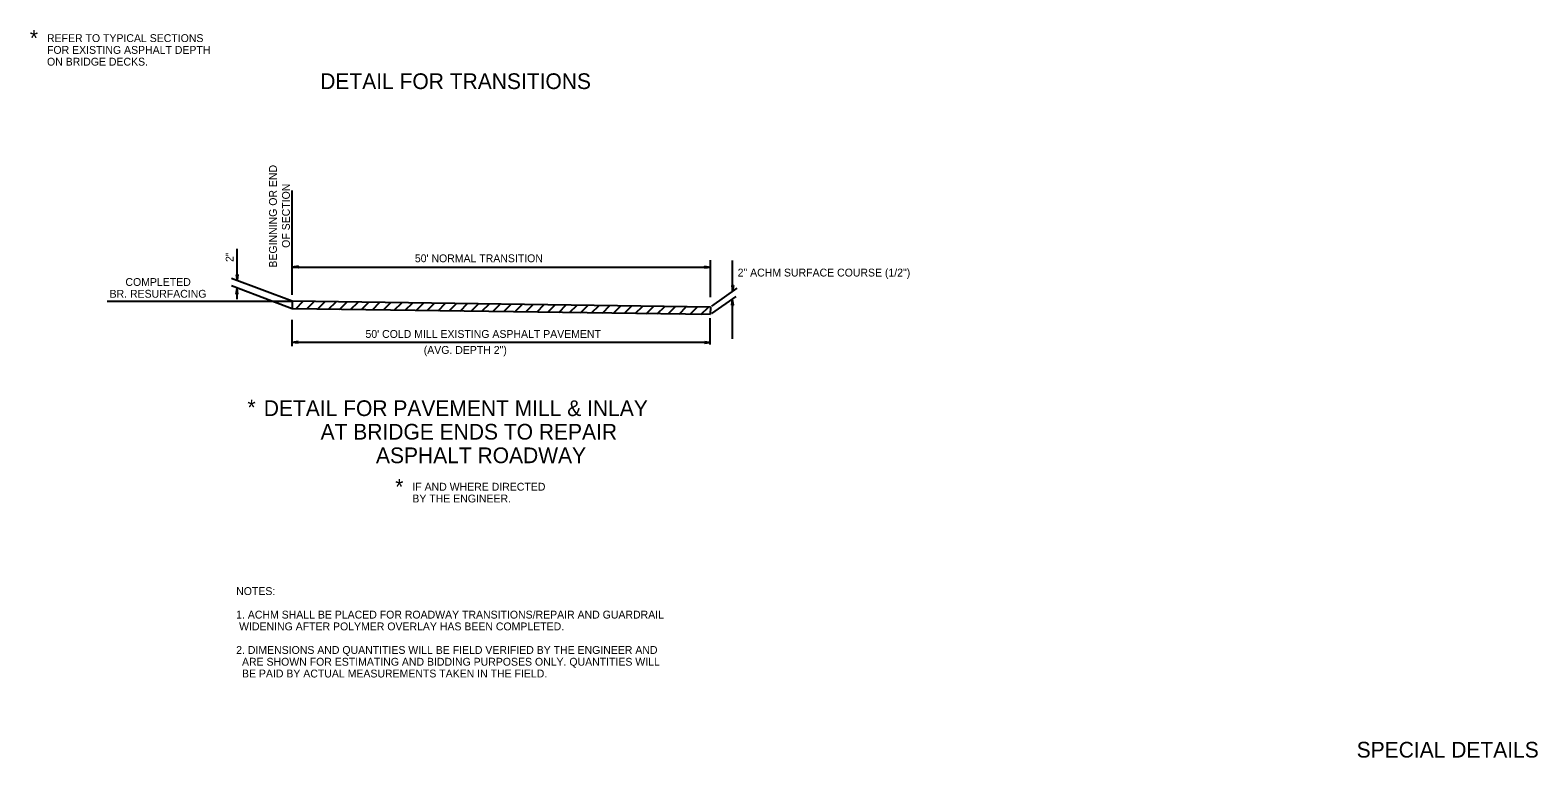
# Model space of a CAD drawing. Extents: x 1931522 to 1935523, y 600380 to 605075.
# Drawn here: x 1933129 to 1934281, y 602208 to 602764 of the extents above; entities that cross this region are included whole.
import ezdxf

# ---------------------------------------------------------------- set-up
doc = ezdxf.new("R2010")
doc.units = 0
doc.layers.add('Default', color=7, linetype='Continuous')
doc.layers.add('R_Border', color=7, linetype='Continuous')

msp = doc.modelspace()

# ---------------------------------------------------------------- linework, layer by layer
at = {"layer": 'Default'}
for p, q in [((1933329.1, 602561.8), (1933329.1, 602641.6)), ((1933286.9, 602573.1), (1933286.9, 602597.1)), ((1933648.6, 602560), (1933648.6, 602588.4)), ((1933665.4, 602564.4), (1933665.4, 602588)), ((1933329.1, 602557.1), (1933282.6, 602574.4)), ((1933286.2, 602577.5), (1933286.9, 602573.1)), ((1933286.2, 602577.5), (1933286.9, 602573.8)), ((1933287.5, 602577.5), (1933286.2, 602577.5)), ((1933286.4, 602577.5), (1933286.9, 602574.7)), ((1933286.4, 602577.5), (1933286.9, 602575.3)), ((1933286.6, 602577.5), (1933286.9, 602576.2)), ((1933286.6, 602577.5), (1933286.9, 602576.9)), ((1933287.5, 602577.5), (1933286.9, 602573.1)), ((1933287.1, 602577.5), (1933286.9, 602576.2)), ((1933287.3, 602577.5), (1933286.9, 602574.7)), ((1933287.3, 602577.5), (1933286.9, 602573.8)), ((1933287.1, 602577.5), (1933286.9, 602575.3)), ((1933286.9, 602577.5), (1933286.9, 602576.9)), ((1933333.7, 602583.8), (1933329.1, 602583.1)), ((1933329.1, 602583.1), (1933648.6, 602583.1)), ((1933333.7, 602582.4), (1933329.1, 602583.1)), ((1933333.7, 602583.5), (1933329.7, 602583.1)), ((1933333.7, 602582.4), (1933329.7, 602583.1)), ((1933333.7, 602583.5), (1933330.6, 602583.1)), ((1933333.7, 602582.6), (1933330.6, 602583.1)), ((1933333.7, 602583.3), (1933331.5, 602583.1)), ((1933333.7, 602582.6), (1933331.5, 602583.1)), ((1933333.7, 602583.3), (1933332.2, 602583.1)), ((1933333.7, 602582.9), (1933332.2, 602583.1)), ((1933333.7, 602583.1), (1933333.1, 602583.1)), ((1933333.7, 602582.9), (1933333.1, 602583.1)), ((1933333.7, 602582.4), (1933333.7, 602583.8)), ((1933643.9, 602583.8), (1933648.6, 602583.1)), ((1933643.9, 602583.8), (1933643.9, 602582.4)), ((1933643.9, 602583.5), (1933647, 602583.1)), ((1933643.9, 602583.5), (1933647.7, 602583.1)), ((1933643.9, 602583.3), (1933645.5, 602583.1)), ((1933643.9, 602583.3), (1933646.1, 602583.1)), ((1933643.9, 602582.4), (1933648.6, 602583.1)), ((1933643.9, 602582.9), (1933645.5, 602583.1)), ((1933643.9, 602582.6), (1933647, 602583.1)), ((1933643.9, 602582.4), (1933647.7, 602583.1)), ((1933643.9, 602582.6), (1933646.1, 602583.1)), ((1933643.9, 602582.9), (1933644.6, 602583.1)), ((1933643.9, 602583.1), (1933644.6, 602583.1)), ((1933313.5, 602557.1), (1933282.6, 602568.7)), ((1933286.2, 602562.4), (1933286.9, 602567.1)), ((1933286.2, 602562.4), (1933286.9, 602566.4)), ((1933286.2, 602562.4), (1933287.5, 602562.4)), ((1933286.4, 602562.4), (1933286.9, 602565.5)), ((1933286.4, 602562.4), (1933286.9, 602564.9)), ((1933286.6, 602562.4), (1933286.9, 602564)), ((1933286.6, 602562.4), (1933286.9, 602563.1)), ((1933287.5, 602562.4), (1933286.9, 602567.1)), ((1933286.9, 602558.7), (1933286.9, 602567.1)), ((1933287.3, 602562.4), (1933286.9, 602566.4)), ((1933287.3, 602562.4), (1933286.9, 602565.5)), ((1933287.1, 602562.4), (1933286.9, 602564.9)), ((1933287.1, 602562.4), (1933286.9, 602564)), ((1933286.9, 602562.4), (1933286.9, 602563.1)), ((1933649.6, 602553.3), (1933669, 602566.9)), ((1933664.8, 602569.1), (1933665.4, 602564.4)), ((1933666.1, 602569.1), (1933664.8, 602569.1)), ((1933665, 602569.1), (1933665.4, 602566)), ((1933665, 602569.1), (1933665.4, 602565.3)), ((1933665.2, 602569.1), (1933665.4, 602567.5)), ((1933665.2, 602569.1), (1933665.4, 602566.9)), ((1933666.1, 602569.1), (1933665.4, 602564.4)), ((1933665.7, 602569.1), (1933665.4, 602567.5)), ((1933665.9, 602569.1), (1933665.4, 602566)), ((1933666.1, 602569.1), (1933665.4, 602565.3)), ((1933665.9, 602569.1), (1933665.4, 602566.9)), ((1933665.4, 602569.1), (1933665.4, 602568.4)), ((1933665.7, 602569.1), (1933665.4, 602568.4)), ((1933187.7, 602557.1), (1933329.1, 602557.1)), ((1933329.1, 602551.3), (1933313.5, 602557.1)), ((1933648.6, 602552.6), (1933329.1, 602557.1)), ((1933648.3, 602546.8), (1933329.1, 602551.3)), ((1933331.7, 602551.3), (1933337.4, 602557)), ((1933340.1, 602551.2), (1933345.8, 602556.9)), ((1933348.5, 602551.1), (1933354.2, 602556.7)), ((1933356.8, 602550.9), (1933362.5, 602556.6)), ((1933365.2, 602550.8), (1933370.9, 602556.5)), ((1933373.6, 602550.7), (1933379.3, 602556.4)), ((1933381.9, 602550.6), (1933387.6, 602556.3)), ((1933390.3, 602550.5), (1933396, 602556.2)), ((1933398.7, 602550.4), (1933404.4, 602556)), ((1933407, 602550.2), (1933412.7, 602555.9)), ((1933415.4, 602550.1), (1933421.1, 602555.8)), ((1933423.8, 602550), (1933429.5, 602555.7)), ((1933432.1, 602549.9), (1933437.8, 602555.6)), ((1933440.5, 602549.8), (1933446.2, 602555.5)), ((1933448.9, 602549.6), (1933454.6, 602555.3)), ((1933457.3, 602549.5), (1933462.9, 602555.2)), ((1933465.6, 602549.4), (1933471.3, 602555.1)), ((1933474, 602549.3), (1933479.7, 602555)), ((1933482.4, 602549.2), (1933488.1, 602554.9)), ((1933490.7, 602549.1), (1933496.4, 602554.8)), ((1933499.1, 602548.9), (1933504.8, 602554.6)), ((1933507.5, 602548.8), (1933513.2, 602554.5)), ((1933515.8, 602548.7), (1933521.5, 602554.4)), ((1933524.2, 602548.6), (1933529.9, 602554.3)), ((1933532.6, 602548.5), (1933538.3, 602554.2)), ((1933540.9, 602548.4), (1933546.6, 602554.1)), ((1933549.3, 602548.2), (1933555, 602553.9)), ((1933557.7, 602548.1), (1933563.4, 602553.8)), ((1933566, 602548), (1933571.7, 602553.7)), ((1933574.4, 602547.9), (1933580.1, 602553.6)), ((1933582.8, 602547.8), (1933588.5, 602553.5)), ((1933591.1, 602547.6), (1933596.8, 602553.3)), ((1933599.5, 602547.5), (1933605.2, 602553.2)), ((1933607.9, 602547.4), (1933613.6, 602553.1)), ((1933616.2, 602547.3), (1933621.9, 602553)), ((1933624.6, 602547.2), (1933630.3, 602552.9)), ((1933633, 602547.1), (1933638.7, 602552.8)), ((1933641.3, 602546.9), (1933647, 602552.6)), ((1933648.6, 602552.7), (1933648.3, 602546.9)), ((1933649.5, 602547.7), (1933668.1, 602560.6)), ((1933664.8, 602554), (1933665.4, 602558.7)), ((1933664.8, 602554), (1933666.1, 602554)), ((1933665, 602554), (1933665.4, 602558)), ((1933665, 602554), (1933665.4, 602557.1)), ((1933665.2, 602554), (1933665.4, 602556.4)), ((1933665.2, 602554), (1933665.4, 602555.5)), ((1933665.4, 602528.4), (1933665.4, 602558.7)), ((1933666.1, 602554), (1933665.4, 602558.7)), ((1933666.1, 602554), (1933665.4, 602558)), ((1933665.9, 602554), (1933665.4, 602557.1)), ((1933665.9, 602554), (1933665.4, 602556.4)), ((1933665.7, 602554), (1933665.4, 602555.5)), ((1933665.7, 602554), (1933665.4, 602554.9)), ((1933665.4, 602554), (1933665.4, 602554.9)), ((1933329.1, 602522.7), (1933329.1, 602542.7)), ((1933648.3, 602524), (1933648.3, 602544)), ((1933333.5, 602526.2), (1933329.1, 602525.6)), ((1933333.5, 602526.2), (1933329.1, 602525.6)), ((1933648.3, 602525.6), (1933329.1, 602525.6)), ((1933333.5, 602524.9), (1933329.1, 602525.6)), ((1933333.5, 602524.9), (1933329.1, 602525.6)), ((1933333.5, 602526.2), (1933329.7, 602525.6)), ((1933333.5, 602526.2), (1933329.7, 602525.6)), ((1933333.5, 602525.1), (1933329.7, 602525.6)), ((1933333.5, 602525.1), (1933329.7, 602525.6)), ((1933333.5, 602526), (1933330.6, 602525.6)), ((1933333.5, 602526), (1933330.6, 602525.6)), ((1933333.5, 602525.1), (1933330.6, 602525.6)), ((1933333.5, 602525.1), (1933330.6, 602525.6)), ((1933333.5, 602526), (1933331.3, 602525.6)), ((1933333.5, 602526), (1933331.3, 602525.6)), ((1933333.5, 602525.3), (1933331.3, 602525.6)), ((1933333.5, 602525.3), (1933331.3, 602525.6)), ((1933333.5, 602525.8), (1933332.2, 602525.6)), ((1933333.5, 602525.8), (1933332.2, 602525.6)), ((1933333.5, 602525.3), (1933332.2, 602525.6)), ((1933333.5, 602525.3), (1933332.2, 602525.6)), ((1933333.5, 602525.8), (1933332.8, 602525.6)), ((1933333.5, 602525.8), (1933332.8, 602525.6)), ((1933333.5, 602525.6), (1933332.8, 602525.6)), ((1933333.5, 602525.6), (1933332.8, 602525.6)), ((1933333.5, 602524.9), (1933333.5, 602526.2)), ((1933333.5, 602524.9), (1933333.5, 602526.2)), ((1933643.9, 602526.2), (1933648.3, 602525.6)), ((1933643.9, 602526.2), (1933647.7, 602525.6)), ((1933643.9, 602526.2), (1933643.9, 602524.9)), ((1933643.9, 602526), (1933646.8, 602525.6)), ((1933643.9, 602526), (1933646.1, 602525.6)), ((1933643.9, 602525.8), (1933645.2, 602525.6)), ((1933643.9, 602525.8), (1933644.6, 602525.6)), ((1933643.9, 602524.9), (1933648.3, 602525.6)), ((1933643.9, 602525.3), (1933645.2, 602525.6)), ((1933643.9, 602525.1), (1933646.8, 602525.6)), ((1933643.9, 602525.1), (1933647.7, 602525.6)), ((1933643.9, 602525.3), (1933646.1, 602525.6)), ((1933643.9, 602525.6), (1933644.6, 602525.6))]:
    msp.add_line(p, q, dxfattribs=at)
at = {"layer": 'R_Border'}
msp.add_line((1933329.1, 602557.1), (1933329.1, 602551.3), dxfattribs=at)

# ---------------------------------------------------------------- texts
at = {"layer": 'Default'}
for s, height, rotation, p in [('DETAIL FOR TRANSITIONS', 12, 360, (1933350.4, 602719.1)), ('BEGINNING OR END', 6, 90, (1933317.3, 602582.7)), ('OF SECTION', 6, 90, (1933327.2, 602597.8)), ('2"', 6, 90, (1933284.2, 602587)), ("50' NORMAL TRANSITION", 6, 360, (1933422.7, 602586.8)), ('COMPLETED', 6, 360, (1933201.6, 602568.7)), ('BR. RESURFACING', 6, 360, (1933189.5, 602559.7)), ("50' COLD MILL EXISTING ASPHALT PAVEMENT", 6, 360, (1933385, 602529)), ('(AVG. DEPTH 2")', 6, 360, (1933429.5, 602516.8))]:
    msp.add_text(s, height=height, rotation=rotation, dxfattribs=at).set_placement(p)
msp.add_text('2" ACHM SURFACE COURSE (1/2")', height=6, dxfattribs=at).set_placement((1933669.3, 602575.9))
at = {"layer": 'R_Border'}
for s, height, p in [('*', 12, (1933128.6, 602752.1)), ('REFER TO TYPICAL SECTIONS', 6, (1933141.7, 602755)), ('FOR EXISTING ASPHALT DEPTH ', 6, (1933141.7, 602746)), ('ON BRIDGE DECKS.', 6, (1933141.7, 602737)), ('*', 12, (1933294.8, 602469.9)), ('DETAIL FOR PAVEMENT MILL & INLAY', 12, (1933307.3, 602469.3)), ('AT BRIDGE ENDS TO REPAIR', 12, (1933350.7, 602451.3)), ('ASPHALT ROADWAY', 12, (1933393, 602433.3)), ('*', 12, (1933407.7, 602409.3)), ('IF AND WHERE DIRECTED', 6, (1933420.8, 602412.3)), ('BY THE ENGINEER.', 6, (1933420.8, 602403.3)), ('NOTES:', 6, (1933286.2, 602332.6)), ('1. ACHM SHALL BE PLACED FOR ROADWAY TRANSITIONS/REPAIR AND GUARDRAIL', 6, (1933286.2, 602314.6)), (' WIDENING AFTER POLYMER OVERLAY HAS BEEN COMPLETED.', 6, (1933286.2, 602305.6)), ('2. DIMENSIONS AND QUANTITIES WILL BE FIELD VERIFIED BY THE ENGINEER AND ', 6, (1933286.2, 602287.6)), ('  ARE SHOWN FOR ESTIMATING AND BIDDING PURPOSES ONLY. QUANTITIES WILL', 6, (1933286.2, 602278.6)), ('  BE PAID BY ACTUAL MEASUREMENTS TAKEN IN THE FIELD.', 6, (1933286.2, 602269.6)), ('SPECIAL DETAILS', 12, (1934142.2, 602208.4))]:
    msp.add_text(s, height=height, rotation=360, dxfattribs=at).set_placement(p)

doc.saveas('drawing.dxf')
